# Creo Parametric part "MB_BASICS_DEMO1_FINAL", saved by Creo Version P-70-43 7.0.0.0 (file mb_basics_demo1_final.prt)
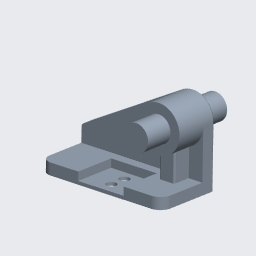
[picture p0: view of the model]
Units: millimeter Kilogram Sec (mmKs); MM, KILOGRAM, SECS

Created from: INLBS_PART_SOLID.PRT

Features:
  1. datum plane "RIGHT"
  2. datum plane "TOP"
  3. datum plane "FRONT"
  4. coordinate system
  5. sketch "Sketch 1"
  6. sketch "Sketch 2"
  7. extrusion "Extrude 1"
  8. extruded cut "Extrude 2"
  9. extruded cut "Extrude 3"
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
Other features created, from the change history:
  extrusion "Extrude 1" (2 times)
  extrusion "Extrude 2"
  extrusion "Extrude 4"
  extrusion "Extrude 5"
  extrusion "Extrude 6"
  round "Round 1"
  round "Round 2"
  round "Round 3"
  shell "Shell 1"
  extrusion "Extrude 7" (3 times)
  feature "Body Merge 1" (2 times)

Surfaces: 27 plane, 24 cylinder, 2 torus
